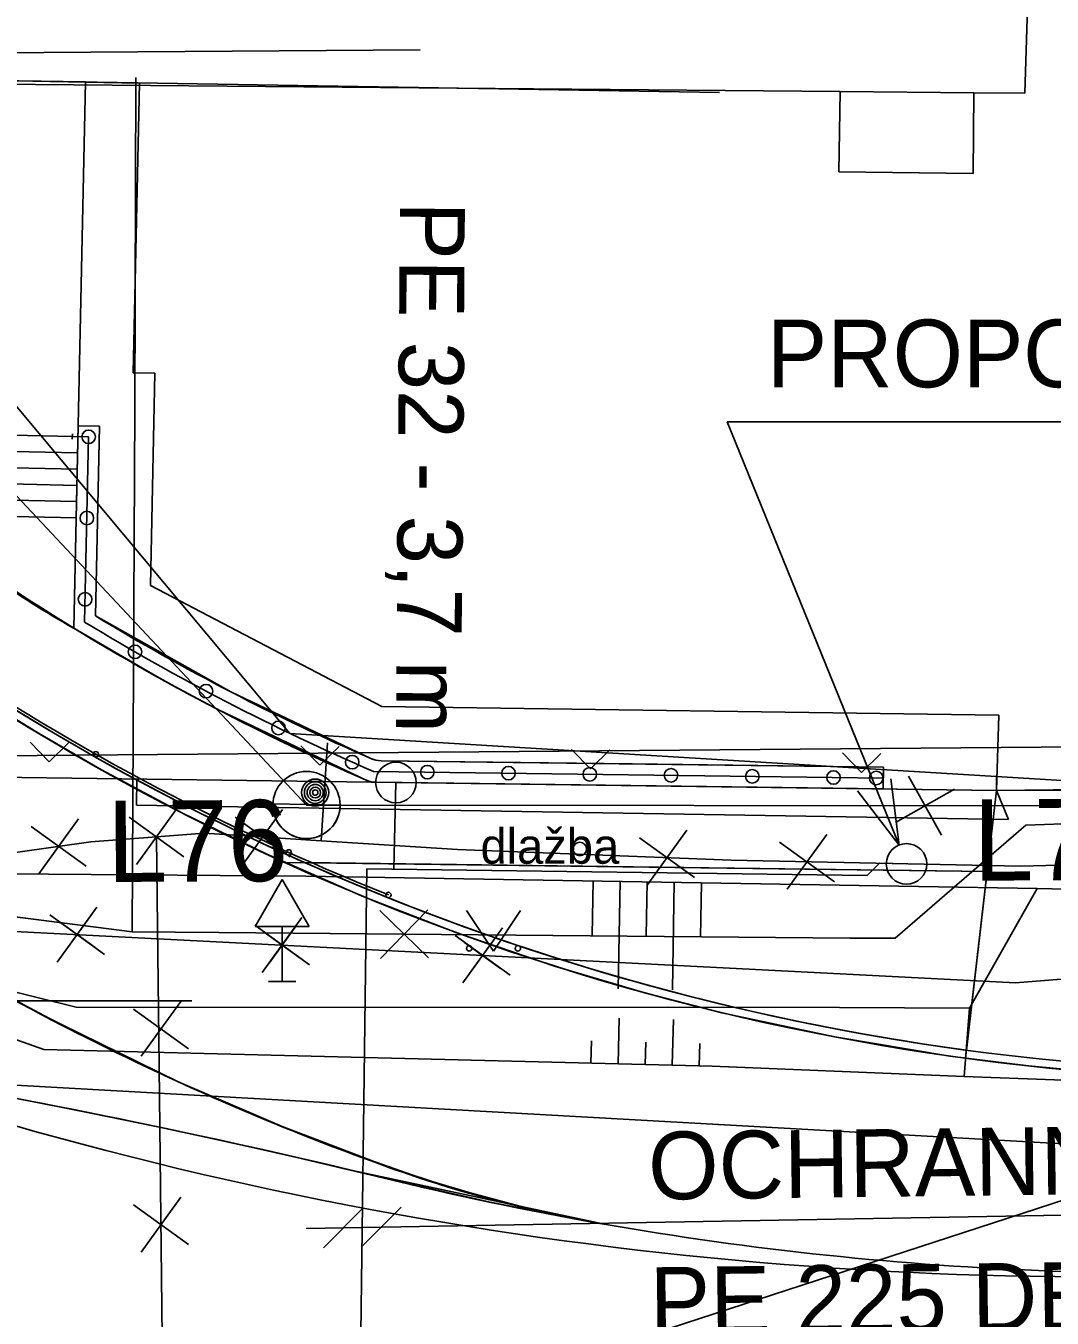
# Model space of a CAD drawing. Extents: x -643342 to -638635, y -1201752 to -1189948.
# Drawn here: x -639472.65 to -639453.7, y -1192725.54 to -1192701.69 of the extents above; entities that cross this region are included whole.
import ezdxf

# ---------------------------------------------------------------- set-up
doc = ezdxf.new("R2010")
doc.units = 0
for name, color, linetype in [('-zbytky_kruháče', 7, 'Continuous'), ('2', 7, 'Continuous'), ('42', 7, 'Continuous'), ('IS_EL_NN_NADZEMNÍ', 7, 'Continuous'), ('IS_PLYN_STL', 7, 'Continuous'), ('IS_TELEF_MISTNI_ZAMERENO', 7, 'Continuous'), ('IS_VODOVOD_VAS', 7, 'Continuous'), ('K-HRANICE_KN', 7, 'Continuous'), ('K-SLUCKOVE CARY', 7, 'Continuous'), ('N-CHODNIK', 7, 'Continuous'), ('N-CHODNIK-PŘÍMĚTICE', 7, 'Continuous'), ('N-KAN_DEST_TRASA-NÁVRH', 7, 'Continuous'), ('N-OBVOD STAVBY 06', 7, 'Continuous'), ('N-oploceni', 7, 'Continuous'), ('N-OSA', 7, 'Continuous'), ('N-rusene_vedeni', 7, 'Continuous'), ('N-SILNICE', 7, 'Continuous'), ('N-SRAFY_PLOCHY', 7, 'Continuous'), ('N-ZDI', 7, 'Continuous'), ('N-úprava plochu u obecního úřadu', 7, 'Continuous'), ('RWE_STL_PRIPOJKY', 7, 'Continuous'), ('RWE_STL_RADY', 7, 'Continuous'), ('tomaštík - Džuganovi - Vrstva 36', 7, 'Continuous'), ('Vrstva 46', 7, 'Continuous'), ('Z-budovy', 7, 'Continuous'), ('Z-hrany_a_čáry', 7, 'Continuous'), ('Z-popisy', 7, 'Continuous'), ('Z-sloupy', 7, 'Continuous'), ('Z-vchody_vjezdy', 7, 'Continuous'), ('Z-značky', 7, 'Continuous')]:
    doc.layers.add(name, color=color, linetype=linetype)

# ---------------------------------------------------------------- blocks, each defined once
blk = doc.blocks.new('zs')
at = {"layer": 'N-oploceni'}
blk.add_circle((0, 0), 0.05, dxfattribs=at)

msp = doc.modelspace()

# ---------------------------------------------------------------- linework, layer by layer
at = {"layer": '-zbytky_kruháče'}
for centre, radius, start, end in [((-639449.284, -1192676.149), 49.5, 234.0867, 250.3224), ((-639498.752, -1192857.717), 138.675, 76.30745, 79.93893), ((-639451.547, -1192663.966), 60.744, 255.88064, 271.68016), ((-639457.831, -1192700.049), 24.118, 250.3224, 260.1216)]:
    msp.add_arc(centre, radius, start, end, dxfattribs=at)
at = {"layer": '2'}
msp.add_line((-639514.564, -1192719.686), (-639469.586, -1192719.686), dxfattribs=at)
for centre in [(-639465.819, -1192715.655), (-639456.391, -1192717.157)]:
    msp.add_circle(centre, 0.375, dxfattribs=at)
at = {"layer": '42'}
for p, q in [((-639511.045, -1192702.433), (-639465.369, -1192702.13)), ((-639406.06, -1192708.997), (-639459.706, -1192708.997)), ((-639459.706, -1192708.997), (-639456.529, -1192716.808)), ((-639456.529, -1192716.808), (-639456.682, -1192715.584)), ((-639456.529, -1192716.808), (-639457.296, -1192715.806)), ((-639467.478, -1192723.887), (-639437.81, -1192723.371)), ((-639467.159, -1192724.244), (-639466.426, -1192723.505)), ((-639466.459, -1192724.232), (-639465.725, -1192723.493))]:
    msp.add_line(p, q, dxfattribs=at)
at = {"layer": 'IS_EL_NN_NADZEMNÍ'}
for p, q in [((-639467.47, -1192716.07), (-639488.19, -1192693.98)), ((-639435.16, -1192716.11), (-639467.47, -1192716.07)), ((-639472.79, -1192729.64), (-639435.08, -1192717.37))]:
    msp.add_line(p, q, dxfattribs=at)
for points in [[(-639485.829, -1192693.153), (-639467.777, -1192714.748)], [(-639467.777, -1192714.748), (-639435.223, -1192716.731)], [(-639468.09, -1192716.047), (-639466.85, -1192716.073)], [(-639466.85, -1192716.073), (-639468.09, -1192716.047)]]:
    msp.add_lwpolyline(points, dxfattribs=at)
msp.add_circle((-639467.47, -1192716.07), 0.62, dxfattribs=at)
for centre, radius, start, end in [((-639467.47, -1192716.07), 0.62, 177.8747, 358.7938), ((-639467.443, -1192716.068), 0.593, 358.5972, 359.5214)]:
    msp.add_arc(centre, radius, start, end, dxfattribs=at)
at = {"layer": 'IS_PLYN_STL'}
msp.add_line((-639467.08, -1192714.92), (-639467.2, -1192716.73), dxfattribs=at)
for points in [[(-639470.24, -1192716.66), (-639471.45, -1192716.75), (-639474.85, -1192717.23), (-639477.45, -1192717.59), (-639486.49, -1192709.11), (-639487.46, -1192707.33), (-639488.82, -1192705.38), (-639489.11, -1192702.85), (-639489.56, -1192702.88), (-639501.83, -1192703.9), (-639502.31, -1192703.92), (-639507.74, -1192703.7), (-639509.62, -1192703.19), (-639512.37, -1192701.73)], [(-639403.51, -1192714.1), (-639415.41, -1192715.24), (-639448.18, -1192717.04), (-639454.29, -1192717.2), (-639459.63, -1192717.09), (-639464.68, -1192716.89), (-639467.2, -1192716.73), (-639469.36, -1192716.59), (-639470.24, -1192716.66)], [(-639470.24, -1192716.66), (-639470.23, -1192717.78), (-639470.19, -1192720.9), (-639470.11, -1192728.12), (-639470.1, -1192728.47)]]:
    msp.add_lwpolyline(points, dxfattribs=at)
at = {"layer": 'IS_TELEF_MISTNI_ZAMERENO'}
for p, q in [((-639470.64, -1192708.75), (-639470.62, -1192702.64)), ((-639470.69, -1192718.41), (-639470.64, -1192708.75)), ((-639454.19, -1192716.44), (-639450.1, -1192716.3)), ((-639450.1, -1192716.3), (-639454.19, -1192716.44)), ((-639456.6, -1192718.53), (-639454.19, -1192716.44)), ((-639476.13, -1192717.71), (-639470.69, -1192718.41)), ((-639470.69, -1192718.41), (-639476.13, -1192717.71)), ((-639470.69, -1192718.41), (-639469.09, -1192718.42)), ((-639469.09, -1192718.42), (-639457.44, -1192718.53)), ((-639457.44, -1192718.53), (-639456.6, -1192718.53))]:
    msp.add_line(p, q, dxfattribs=at)
at = {"layer": 'IS_VODOVOD_VAS'}
msp.add_lwpolyline([(-639500.03, -1192699), (-639491.62, -1192697.56), (-639487.83, -1192708.11), (-639475.26, -1192718.28), (-639454.38, -1192719.35), (-639371.54, -1192712.72), (-639371.31, -1192712.71), (-639361.553, -1192711.318)], dxfattribs=at)
at = {"layer": 'K-HRANICE_KN'}
msp.add_line((-639430.11, -1192714.81), (-639485.5, -1192715.26), dxfattribs=at)
at = {"layer": 'K-SLUCKOVE CARY'}
for p, q in [((-639454.21, -1192702.93), (-639453.88, -1192692.51)), ((-639474.54, -1192702.75), (-639457.62, -1192702.9)), ((-639457.64, -1192704.38), (-639457.62, -1192702.9)), ((-639457.62, -1192702.9), (-639455.15, -1192702.92)), ((-639455.15, -1192702.92), (-639455.16, -1192704.41)), ((-639455.15, -1192702.92), (-639454.21, -1192702.93)), ((-639455.16, -1192704.41), (-639457.64, -1192704.38))]:
    msp.add_line(p, q, dxfattribs=at)
at = {"layer": 'N-CHODNIK'}
for p, q in [((-639474.553, -1192702.67), (-639471.552, -1192702.72)), ((-639471.552, -1192702.72), (-639471.769, -1192712.802)), ((-639471.689, -1192709.068), (-639471.289, -1192709.077)), ((-639471.289, -1192709.077), (-639471.364, -1192712.58)), ((-639474.698, -1192709.504), (-639471.699, -1192709.568)), ((-639474.705, -1192709.804), (-639471.706, -1192709.868)), ((-639474.711, -1192710.104), (-639471.712, -1192710.168)), ((-639474.717, -1192710.403), (-639471.719, -1192710.468)), ((-639474.724, -1192710.703), (-639471.725, -1192710.768))]:
    msp.add_line(p, q, dxfattribs=at)
msp.add_lwpolyline([(-639455.303, -1192720.745), (-639454.73, -1192715.8), (-639450.17, -1192715.78), (-639448.235, -1192721.137)], dxfattribs=at)
at = {"layer": 'N-CHODNIK-PŘÍMĚTICE'}
msp.add_arc((-639449.284, -1192676.149), 43, 238.4726, 246.5882, dxfattribs=at)
at = {"layer": 'N-KAN_DEST_TRASA-NÁVRH'}
msp.add_lwpolyline([(-639355.755, -1192712.633), (-639405.298, -1192719.503), (-639444.905, -1192722.803), (-639490.998, -1192720.223), (-639511.439, -1192713.331)], dxfattribs=at)
at = {"layer": 'N-OBVOD STAVBY 06'}
for p, q in [((-639470.553, -1192702.741), (-639474.551, -1192702.67)), ((-639470.668, -1192708.09), (-639470.553, -1192702.741)), ((-639470.268, -1192708.098), (-639470.668, -1192708.09)), ((-639470.352, -1192712.02), (-639470.268, -1192708.098)), ((-639466.079, -1192714.251), (-639470.352, -1192712.02)), ((-639454.688, -1192714.408), (-639466.079, -1192714.251)), ((-639454.73, -1192715.8), (-639454.688, -1192714.408)), ((-639449.125, -1192715.732), (-639454.73, -1192715.8)), ((-639454.73, -1192715.8), (-639454.73, -1192715.8))]:
    msp.add_line(p, q, dxfattribs=at)
at = {"layer": 'N-oploceni'}
for p, q in [((-639474.892, -1192709.199), (-639471.493, -1192709.272)), ((-639471.792, -1192709.216), (-639471.794, -1192709.316)), ((-639456.821, -1192715.573), (-639466.235, -1192715.449))]:
    msp.add_line(p, q, dxfattribs=at)
msp.add_lwpolyline([(-639471.493, -1192709.272), (-639471.567, -1192712.691)], dxfattribs=at)
for centre in [(-639471.493, -1192709.272), (-639471.525, -1192710.772), (-639471.558, -1192712.272), (-639470.637, -1192713.242), (-639469.324, -1192713.967), (-639467.987, -1192714.646), (-639466.626, -1192715.278), (-639465.239, -1192715.462), (-639463.74, -1192715.482), (-639462.24, -1192715.502), (-639460.74, -1192715.521), (-639459.24, -1192715.541), (-639457.74, -1192715.561), (-639456.951, -1192715.571), (-639462.424, -1192716.882)]:
    msp.add_circle(centre, 0.125, dxfattribs=at)
for radius, start, end in [(42.8, 238.6261, 246.6688), (44.8, 235.416, 248.1495)]:
    msp.add_arc((-639449.284, -1192676.149), radius, start, end, dxfattribs=at)
at = {"layer": 'N-OSA'}
msp.add_arc((-639452.868, -1192651.78), 73, 249.0487, 271.88891, dxfattribs=at)
at = {"layer": 'N-rusene_vedeni'}
for p, q in [((-639456.358, -1192715.54), (-639455.743, -1192716.628)), ((-639456.594, -1192716.392), (-639455.506, -1192715.776)), ((-639470.747, -1192716.294), (-639469.733, -1192717.026)), ((-639469.874, -1192716.153), (-639470.606, -1192717.167)), ((-639468.787, -1192716.294), (-639467.773, -1192717.026)), ((-639467.914, -1192716.153), (-639468.646, -1192717.167)), ((-639472.552, -1192716.468), (-639471.539, -1192717.2)), ((-639471.68, -1192716.327), (-639472.411, -1192717.341)), ((-639460.448, -1192716.536), (-639461.18, -1192717.55)), ((-639461.321, -1192716.677), (-639460.308, -1192717.409)), ((-639458.736, -1192716.753), (-639457.723, -1192717.485)), ((-639457.864, -1192716.612), (-639458.595, -1192717.626)), ((-639471.339, -1192717.955), (-639472.071, -1192718.969)), ((-639472.212, -1192718.096), (-639471.199, -1192718.828)), ((-639472.037, -1192718.222), (-639471.373, -1192718.702)), ((-639471.466, -1192718.13), (-639471.945, -1192718.794)), ((-639467.554, -1192718.149), (-639468.286, -1192719.163)), ((-639465.219, -1192718.888), (-639466.115, -1192718.016)), ((-639466.103, -1192718.9), (-639465.231, -1192718.005)), ((-639468.427, -1192718.29), (-639467.413, -1192719.022)), ((-639468.252, -1192718.416), (-639467.588, -1192718.896)), ((-639467.68, -1192718.324), (-639468.16, -1192718.988)), ((-639463.853, -1192718.339), (-639464.585, -1192719.353)), ((-639464.726, -1192718.48), (-639463.712, -1192719.212)), ((-639464.551, -1192718.606), (-639463.887, -1192719.085)), ((-639463.979, -1192718.514), (-639464.459, -1192719.178)), ((-639470.664, -1192719.836), (-639469.651, -1192720.568)), ((-639469.792, -1192719.695), (-639470.523, -1192720.709)), ((-639470.664, -1192723.452), (-639469.651, -1192724.184)), ((-639469.792, -1192723.311), (-639470.523, -1192724.325))]:
    msp.add_line(p, q, dxfattribs=at)
at = {"layer": 'N-SILNICE'}
for p, q in [((-639456.818, -1192715.373), (-639466.092, -1192715.251)), ((-639456.823, -1192715.773), (-639456.818, -1192715.373)), ((-639454.73, -1192715.8), (-639466.177, -1192715.65)), ((-639454.73, -1192715.8), (-639455.303, -1192720.745)), ((-639454.904, -1192717.298), (-639467.878, -1192717.128))]:
    msp.add_line(p, q, dxfattribs=at)
msp.add_lwpolyline([(-639466.365, -1192722.875), (-639461.978, -1192723.807)], dxfattribs=at)
for centre, radius, start, end in [((-639449.284, -1192676.149), 45, 235.416, 271.6812), ((-639449.284, -1192676.149), 44.85, 235.416, 262.3092), ((-639449.284, -1192676.149), 44.85, 235.416, 271.2718), ((-639466.085, -1192714.751), 0.5, 246.4794, 269.2497), ((-639466.171, -1192715.15), 0.5, 246.5882, 269.2497), ((-639449.284, -1192676.149), 49.5, 234.0867, 250.3224), ((-639499.303, -1192860.56), 141.57, 76.54628, 79.92036), ((-639457.831, -1192700.049), 24.118, 250.3224, 260.0975)]:
    msp.add_arc(centre, radius, start, end, dxfattribs=at)
at = {"layer": 'N-SRAFY_PLOCHY'}
for p, q in [((-639471.552, -1192702.72), (-639474.552, -1192702.67)), ((-639471.769, -1192712.802), (-639471.552, -1192702.72)), ((-639471.689, -1192709.068), (-639471.769, -1192712.802)), ((-639471.289, -1192709.077), (-639471.689, -1192709.068)), ((-639471.364, -1192712.58), (-639471.289, -1192709.077)), ((-639468.869, -1192713.98), (-639471.364, -1192712.58)), ((-639471.769, -1192712.802), (-639470.085, -1192713.783)), ((-639470.085, -1192713.783), (-639469.119, -1192714.301)), ((-639472.421, -1192714.745), (-639473.628, -1192713.995)), ((-639466.285, -1192715.21), (-639468.869, -1192713.98)), ((-639469.119, -1192714.301), (-639466.357, -1192715.614)), ((-639471.254, -1192715.421), (-639472.421, -1192714.745)), ((-639466.19, -1192715.24), (-639466.285, -1192715.21)), ((-639466.092, -1192715.251), (-639466.19, -1192715.24)), ((-639461.455, -1192715.312), (-639466.092, -1192715.251)), ((-639456.818, -1192715.373), (-639461.455, -1192715.312)), ((-639469.761, -1192716.219), (-639471.254, -1192715.421)), ((-639456.823, -1192715.773), (-639456.818, -1192715.373)), ((-639466.357, -1192715.614), (-639466.275, -1192715.639)), ((-639454.73, -1192715.8), (-639466.277, -1192715.649)), ((-639466.275, -1192715.639), (-639466.177, -1192715.65)), ((-639466.177, -1192715.65), (-639464.275, -1192715.675)), ((-639464.275, -1192715.675), (-639456.823, -1192715.773)), ((-639454.73, -1192715.8), (-639455.303, -1192720.745)), ((-639454.904, -1192717.298), (-639454.73, -1192715.8)), ((-639450.17, -1192715.78), (-639454.73, -1192715.8)), ((-639468.203, -1192716.978), (-639469.761, -1192716.219)), ((-639466.41, -1192717.762), (-639468.203, -1192716.978)), ((-639467.878, -1192717.128), (-639454.904, -1192717.298)), ((-639467.501, -1192717.133), (-639454.904, -1192717.298)), ((-639454.904, -1192717.298), (-639455.286, -1192720.596)), ((-639464.697, -1192718.427), (-639466.41, -1192717.762)), ((-639462.889, -1192719.043), (-639464.697, -1192718.427)), ((-639461.202, -1192719.542), (-639462.889, -1192719.043)), ((-639473.229, -1192719.472), (-639471.716, -1192720.274)), ((-639459.799, -1192719.903), (-639461.202, -1192719.542)), ((-639457.715, -1192720.352), (-639459.799, -1192719.903)), ((-639471.716, -1192720.274), (-639469.84, -1192721.178)), ((-639455.591, -1192720.704), (-639457.715, -1192720.352)), ((-639454.139, -1192720.886), (-639455.591, -1192720.704)), ((-639455.303, -1192720.745), (-639454.083, -1192720.892)), ((-639452.545, -1192721.03), (-639454.139, -1192720.886)), ((-639454.083, -1192720.892), (-639452.806, -1192721.011)), ((-639469.84, -1192721.178), (-639467.918, -1192722.007)), ((-639471.837, -1192721.679), (-639473.038, -1192721.447)), ((-639470.533, -1192721.943), (-639471.837, -1192721.679)), ((-639469.035, -1192722.263), (-639470.533, -1192721.943)), ((-639467.918, -1192722.007), (-639465.952, -1192722.758)), ((-639467.404, -1192722.632), (-639469.035, -1192722.263)), ((-639465.926, -1192722.983), (-639467.404, -1192722.632)), ((-639465.952, -1192722.758), (-639464.838, -1192723.126)), ((-639464.08, -1192723.402), (-639465.926, -1192722.983)), ((-639464.838, -1192723.126), (-639463.305, -1192723.537)), ((-639461.98, -1192723.807), (-639464.08, -1192723.402)), ((-639463.305, -1192723.537), (-639461.98, -1192723.807))]:
    msp.add_line(p, q, dxfattribs=at)
for points in [[(-639472.367, -1192719.938), (-639474.117, -1192718.966)], [(-639472.841, -1192721.484), (-639471.453, -1192721.756), (-639470.212, -1192722.011), (-639469.216, -1192722.225), (-639467.907, -1192722.516), (-639466.665, -1192722.808), (-639465.926, -1192722.983), (-639465.003, -1192723.193), (-639464.08, -1192723.403), (-639463.392, -1192723.535), (-639461.968, -1192723.809), (-639463.564, -1192723.468), (-639464.384, -1192723.248), (-639465.298, -1192722.974), (-639466.294, -1192722.628), (-639467.918, -1192722.008), (-639469.84, -1192721.179), (-639472.367, -1192719.938)]]:
    msp.add_lwpolyline(points, dxfattribs=at)
for centre, radius, start, end in [((-639463.769, -1192698.406), 16.47, 228.3034, 240.9372), ((-639449.284, -1192676.149), 43, 235.416, 246.7221), ((-639449.284, -1192676.149), 45, 235.416, 245.5943), ((-639449.284, -1192676.149), 44.85, 246.0357, 262.3092)]:
    msp.add_arc(centre, radius, start, end, dxfattribs=at)
at = {"layer": 'N-ZDI'}
msp.add_arc((-639449.284, -1192676.149), 42.6, 238.7808, 246.4794, dxfattribs=at)
at = {"layer": 'RWE_STL_PRIPOJKY'}
msp.add_line((-639465.819, -1192715.655), (-639465.856, -1192717.254), dxfattribs=at)
at = {"layer": 'RWE_STL_RADY'}
msp.add_lwpolyline([(-639456.391, -1192717.157), (-639456.89, -1192717.146), (-639457.119, -1192717.369), (-639466.356, -1192717.248), (-639466.499, -1192728.212), (-639484.493, -1192728.011), (-639503.164, -1192726.268), (-639506.439, -1192723.649), (-639519.474, -1192721.668)], dxfattribs=at)
at = {"layer": 'Z-budovy'}
msp.add_line((-639459.845, -1192702.913), (-639474.552, -1192702.67), dxfattribs=at)
at = {"layer": 'Z-hrany_a_čáry'}
for p, q in [((-639472.224, -1192715.271), (-639472.574, -1192714.912)), ((-639472.224, -1192715.271), (-639471.866, -1192714.922)), ((-639467.225, -1192715.336), (-639467.574, -1192714.978)), ((-639467.225, -1192715.336), (-639466.866, -1192714.987)), ((-639462.225, -1192715.402), (-639462.575, -1192715.043)), ((-639462.225, -1192715.402), (-639461.867, -1192715.052)), ((-639457.226, -1192715.467), (-639457.575, -1192715.109)), ((-639457.226, -1192715.467), (-639456.867, -1192715.118)), ((-639473.82, -1192715.55), (-639454.73, -1192715.8)), ((-639470.61, -1192716.07), (-639470.602, -1192715.592)), ((-639454.73, -1192715.8), (-639454.726, -1192715.5)), ((-639454.73, -1192715.8), (-639454.51, -1192716.34)), ((-639454.51, -1192716.34), (-639470.61, -1192716.07)), ((-639473.03, -1192717.34), (-639467.48, -1192717.38)), ((-639467.48, -1192717.38), (-639453.98, -1192717.61)), ((-639462.179, -1192717.47), (-639462.196, -1192718.47)), ((-639461.679, -1192717.478), (-639461.713, -1192719.466)), ((-639461.179, -1192717.487), (-639461.196, -1192718.487)), ((-639460.679, -1192717.495), (-639460.713, -1192719.483)), ((-639460.179, -1192717.504), (-639460.196, -1192718.504)), ((-639455.23, -1192719.82), (-639453.98, -1192717.61)), ((-639453.98, -1192717.61), (-639452.08, -1192717.65)), ((-639471.72, -1192719.8), (-639473.35, -1192719.4)), ((-639457.63, -1192719.81), (-639471.72, -1192719.8)), ((-639455.23, -1192719.82), (-639457.63, -1192719.81)), ((-639455.33, -1192721.08), (-639455.23, -1192719.82)), ((-639461.718, -1192720.846), (-639461.697, -1192720.006)), ((-639460.718, -1192720.871), (-639460.697, -1192720.031)), ((-639472.32, -1192720.58), (-639473.23, -1192720.26)), ((-639459.98, -1192720.89), (-639472.32, -1192720.58)), ((-639462.218, -1192720.834), (-639462.208, -1192720.424)), ((-639461.218, -1192720.858), (-639461.208, -1192720.449)), ((-639460.218, -1192720.883), (-639460.208, -1192720.474)), ((-639455.33, -1192721.08), (-639459.98, -1192720.89)), ((-639451.65, -1192721.22), (-639455.33, -1192721.08))]:
    msp.add_line(p, q, dxfattribs=at)
at = {"layer": 'Z-sloupy'}
for radius in [0.25, 0.2, 0.15, 0.1, 0.05]:
    msp.add_circle((-639467.31, -1192715.84), radius, dxfattribs=at)
at = {"layer": 'Z-vchody_vjezdy'}
for p, q in [((-639454.731, -1192715.55), (-639454.73, -1192715.8)), ((-639454.73, -1192715.8), (-639450.17, -1192715.78))]:
    msp.add_line(p, q, dxfattribs=at)
at = {"layer": 'Z-značky'}
for p, q in [((-639467.92, -1192717.446), (-639468.42, -1192718.312)), ((-639467.42, -1192718.312), (-639467.92, -1192717.446)), ((-639464.516, -1192718.016), (-639464.016, -1192718.766)), ((-639464.016, -1192718.766), (-639463.516, -1192718.016)), ((-639468.42, -1192718.312), (-639467.42, -1192718.312)), ((-639467.92, -1192718.312), (-639467.92, -1192719.33)), ((-639468.17, -1192719.33), (-639467.67, -1192719.33))]:
    msp.add_line(p, q, dxfattribs=at)
for centre in [(-639464.466, -1192718.716), (-639463.567, -1192718.716)]:
    msp.add_circle(centre, 0.05, dxfattribs=at)

# ---------------------------------------------------------------- block references
at = {"layer": 'N-úprava plochu u obecního úřadu'}
for p, rotation in [((-639471.361, -1192715.132), -29.524066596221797), ((-639469.599, -1192716.078), -26.96621929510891), ((-639467.797, -1192716.945), -24.408371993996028), ((-639465.958, -1192717.731), -21.850524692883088)]:
    msp.add_blockref('zs', p, dxfattribs=dict(at, rotation=rotation))

# ---------------------------------------------------------------- texts
at = {"layer": 'RWE_STL_RADY'}
msp.add_text('PE 32 - 3,7 m', height=1.2, rotation=269.5644, dxfattribs=at).set_placement((-639465.744, -1192704.927))
at = {"layer": 'tomaštík - Džuganovi - Vrstva 36'}
for s, rotation, p in [('PROPOJ DO STÁVAJÍCÍHO STL PLYNOVODU PE d 110', 0.0307, (-639458.971, -1192708.36)), ('OCHRANNÁ TRUBKA ', 0.6993, (-639461.155, -1192723.355)), ('PE 225 DÉLKA 10,3 m', 0.6993, (-639461.125, -1192725.854))]:
    msp.add_text(s, height=1.25, rotation=rotation, dxfattribs=at).set_placement(p)
at = {"layer": 'Vrstva 46'}
for s, p in [('L76', (-639471.152, -1192717.491)), ('L77', (-639455.158, -1192717.467))]:
    msp.add_text(s, height=1.5, rotation=0.301, dxfattribs=at).set_placement(p)
at = {"layer": 'Z-popisy'}
msp.add_text('dlažba', height=0.65, dxfattribs=at).set_placement((-639464.258, -1192717.153))

doc.saveas('drawing.dxf')
